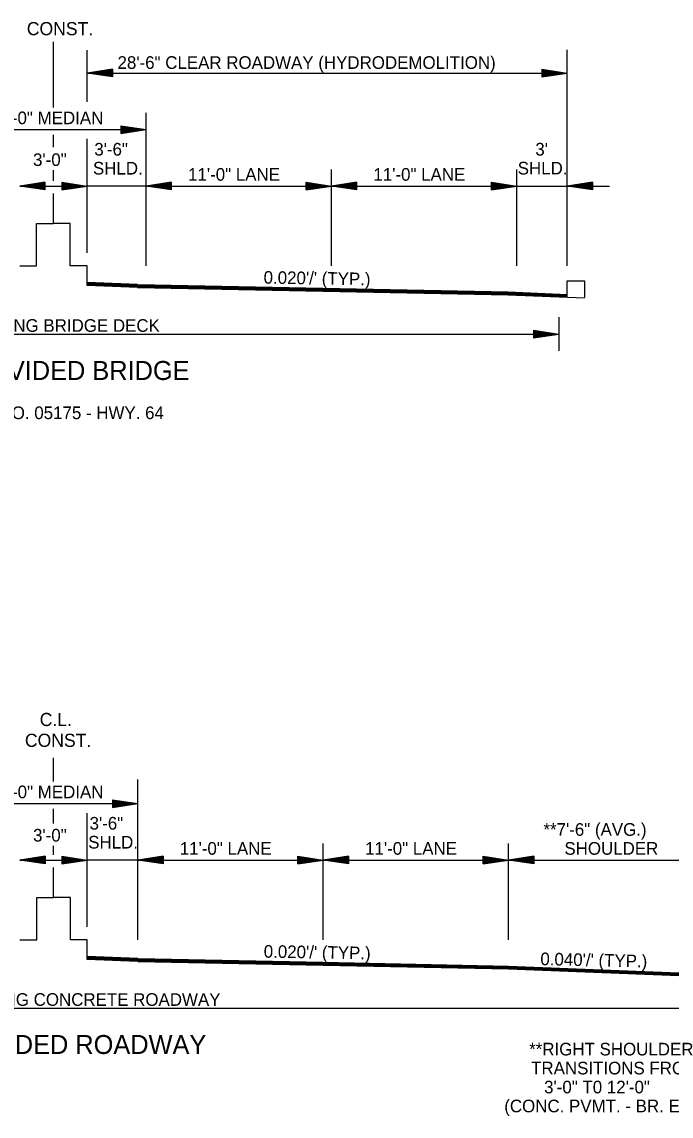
# Model space of a CAD drawing. Extents: x 542112 to 1930787, y -1968972 to 596640.
# Drawn here: x 544863 to 545248, y -1953261 to -1952611 of the extents above; entities that cross this region are included whole.
import ezdxf

# ---------------------------------------------------------------- set-up
doc = ezdxf.new("R2010")
doc.units = 0
doc.layers.add('R_Border', color=7, linetype='Continuous')
doc.layers.add('R_Draft', color=7, linetype='Continuous')

msp = doc.modelspace()

# ---------------------------------------------------------------- linework, layer by layer
at = {"layer": 'R_Border'}
for p, q in [((545186.68, -1952774.54), (545186.68, -1952765.13)), ((545186.68, -1952765.13), (545196.85, -1952765.13)), ((545196.85, -1952765.13), (545196.85, -1952774.95))]:
    msp.add_line(p, q, dxfattribs=at)
at = {"layer": 'R_Draft'}
for p, q in [((544881.74, -1952631.13), (544881.74, -1952623.28)), ((544901.68, -1952658.9), (544901.68, -1952628.12)), ((545186.68, -1952756.22), (545186.68, -1952627.93)), ((544881.74, -1952662.18), (544881.74, -1952631.13)), ((544916.68, -1952639.48), (544901.68, -1952641.73)), ((544916.68, -1952639.86), (544904.19, -1952641.73)), ((544916.68, -1952640.24), (544906.77, -1952641.73)), ((544916.68, -1952640.62), (544909.27, -1952641.73)), ((544916.68, -1952641.01), (544911.81, -1952641.73)), ((544916.68, -1952639.48), (544916.68, -1952643.98)), ((545171.68, -1952639.48), (545186.68, -1952641.73)), ((545171.68, -1952639.48), (545171.68, -1952643.98)), ((545171.68, -1952639.86), (545184.18, -1952641.73)), ((545171.68, -1952640.24), (545181.6, -1952641.73)), ((545171.68, -1952640.62), (545179.1, -1952641.73)), ((545171.68, -1952641.01), (545176.56, -1952641.73)), ((544901.68, -1952641.73), (545181.68, -1952641.73)), ((544916.68, -1952643.98), (544901.68, -1952641.73)), ((544916.68, -1952643.61), (544904.19, -1952641.73)), ((544916.68, -1952643.23), (544906.77, -1952641.73)), ((544916.68, -1952642.85), (544909.27, -1952641.73)), ((544916.68, -1952642.47), (544911.81, -1952641.73)), ((544916.68, -1952641.38), (544914.31, -1952641.73)), ((544916.68, -1952642.09), (544914.31, -1952641.73)), ((545171.68, -1952641.38), (545174.05, -1952641.73)), ((545171.68, -1952643.98), (545186.68, -1952641.73)), ((545171.68, -1952642.47), (545176.56, -1952641.73)), ((545171.68, -1952643.23), (545181.6, -1952641.73)), ((545171.68, -1952643.61), (545184.18, -1952641.73)), ((545171.68, -1952642.85), (545179.1, -1952641.73)), ((545171.68, -1952642.09), (545174.05, -1952641.73)), ((544936.68, -1952756.22), (544936.68, -1952665.38)), ((544921.68, -1952673.02), (544936.68, -1952675.27)), ((544921.68, -1952673.02), (544921.68, -1952677.52)), ((544921.68, -1952673.4), (544934.18, -1952675.27)), ((544831.68, -1952675.27), (544931.68, -1952675.27)), ((544881.68, -1952685.69), (544881.68, -1952678.38)), ((544921.68, -1952673.78), (544931.6, -1952675.27)), ((544921.68, -1952674.15), (544929.1, -1952675.27)), ((544921.68, -1952674.54), (544926.56, -1952675.27)), ((544921.68, -1952674.92), (544924.05, -1952675.27)), ((544921.68, -1952677.52), (544936.68, -1952675.27)), ((544921.68, -1952676.01), (544926.56, -1952675.27)), ((544921.68, -1952676.76), (544931.6, -1952675.27)), ((544921.68, -1952677.15), (544934.18, -1952675.27)), ((544921.68, -1952676.39), (544929.1, -1952675.27)), ((544921.68, -1952675.62), (544924.05, -1952675.27)), ((544901.68, -1952748.49), (544901.68, -1952680.74)), ((544881.68, -1952705.73), (544881.68, -1952699.28)), ((545046.68, -1952756.22), (545046.68, -1952698.92)), ((545156.68, -1952756.22), (545156.68, -1952698.92)), ((544876.68, -1952706.56), (544861.68, -1952708.81)), ((544876.68, -1952711.06), (544861.68, -1952708.81)), ((544861.68, -1952708.81), (544901.68, -1952708.81)), ((544876.68, -1952706.93), (544864.19, -1952708.81)), ((544876.68, -1952710.68), (544864.19, -1952708.81)), ((544876.68, -1952707.32), (544866.77, -1952708.81)), ((544876.68, -1952710.3), (544866.77, -1952708.81)), ((544876.68, -1952707.69), (544869.27, -1952708.81)), ((544876.68, -1952709.93), (544869.27, -1952708.81)), ((544876.68, -1952708.08), (544871.81, -1952708.81)), ((544876.68, -1952709.54), (544871.81, -1952708.81)), ((544876.68, -1952708.46), (544874.31, -1952708.81)), ((544876.68, -1952709.16), (544874.31, -1952708.81)), ((544876.68, -1952706.56), (544876.68, -1952711.06)), ((544886.68, -1952706.56), (544901.68, -1952708.81)), ((544886.68, -1952706.56), (544886.68, -1952711.06)), ((544886.68, -1952706.93), (544899.18, -1952708.81)), ((544886.68, -1952707.32), (544896.6, -1952708.81)), ((544886.68, -1952707.69), (544894.1, -1952708.81)), ((544886.68, -1952708.08), (544891.56, -1952708.81)), ((544886.68, -1952708.46), (544889.05, -1952708.81)), ((544886.68, -1952711.06), (544901.68, -1952708.81)), ((544886.68, -1952709.54), (544891.56, -1952708.81)), ((544886.68, -1952710.3), (544896.6, -1952708.81)), ((544886.68, -1952710.68), (544899.18, -1952708.81)), ((544886.68, -1952709.93), (544894.1, -1952708.81)), ((544886.68, -1952709.16), (544889.05, -1952708.81)), ((544936.68, -1952708.81), (544901.68, -1952708.81)), ((544951.68, -1952706.56), (544936.68, -1952708.81)), ((544951.68, -1952711.06), (544936.68, -1952708.81)), ((544936.68, -1952708.81), (545046.68, -1952708.81)), ((544951.68, -1952706.93), (544939.19, -1952708.81)), ((544951.68, -1952710.68), (544939.19, -1952708.81)), ((544951.68, -1952707.32), (544941.77, -1952708.81)), ((544951.68, -1952710.3), (544941.77, -1952708.81)), ((544951.68, -1952707.69), (544944.27, -1952708.81)), ((544951.68, -1952709.93), (544944.27, -1952708.81)), ((544951.68, -1952708.08), (544946.81, -1952708.81)), ((544951.68, -1952709.54), (544946.81, -1952708.81)), ((544951.68, -1952708.46), (544949.31, -1952708.81)), ((544951.68, -1952709.16), (544949.31, -1952708.81)), ((544951.68, -1952706.56), (544951.68, -1952711.06)), ((545031.68, -1952706.56), (545046.68, -1952708.81)), ((545031.68, -1952711.06), (545031.68, -1952706.56)), ((545031.68, -1952706.93), (545044.18, -1952708.81)), ((545031.68, -1952707.32), (545041.6, -1952708.81)), ((545031.68, -1952707.69), (545039.1, -1952708.81)), ((545031.68, -1952708.07), (545036.56, -1952708.81)), ((545031.68, -1952708.46), (545034.05, -1952708.81)), ((545031.68, -1952711.06), (545046.68, -1952708.81)), ((545031.68, -1952709.54), (545036.56, -1952708.81)), ((545031.68, -1952710.3), (545041.6, -1952708.81)), ((545031.68, -1952710.68), (545044.18, -1952708.81)), ((545031.68, -1952709.93), (545039.1, -1952708.81)), ((545031.68, -1952709.16), (545034.05, -1952708.81)), ((545061.68, -1952706.56), (545046.68, -1952708.81)), ((545061.68, -1952711.06), (545046.68, -1952708.81)), ((545046.68, -1952708.81), (545156.68, -1952708.81)), ((545061.68, -1952706.93), (545049.19, -1952708.81)), ((545061.68, -1952710.68), (545049.19, -1952708.81)), ((545061.68, -1952707.32), (545051.77, -1952708.81)), ((545061.68, -1952710.3), (545051.77, -1952708.81)), ((545061.68, -1952707.69), (545054.27, -1952708.81)), ((545061.68, -1952709.93), (545054.27, -1952708.81)), ((545061.68, -1952708.08), (545056.81, -1952708.81)), ((545061.68, -1952709.54), (545056.81, -1952708.81)), ((545061.68, -1952708.46), (545059.31, -1952708.81)), ((545061.68, -1952709.16), (545059.31, -1952708.81)), ((545061.68, -1952706.56), (545061.68, -1952711.06)), ((545141.68, -1952706.56), (545156.68, -1952708.81)), ((545141.68, -1952711.06), (545141.68, -1952706.56)), ((545141.68, -1952706.93), (545154.18, -1952708.81)), ((545141.68, -1952707.32), (545151.6, -1952708.81)), ((545141.68, -1952707.69), (545149.1, -1952708.81)), ((545141.68, -1952708.07), (545146.56, -1952708.81)), ((545141.68, -1952708.46), (545144.05, -1952708.81)), ((545141.68, -1952711.06), (545156.68, -1952708.81)), ((545141.68, -1952709.54), (545146.56, -1952708.81)), ((545141.68, -1952710.3), (545151.6, -1952708.81)), ((545141.68, -1952710.68), (545154.18, -1952708.81)), ((545141.68, -1952709.93), (545149.1, -1952708.81)), ((545141.68, -1952709.16), (545144.05, -1952708.81)), ((545156.68, -1952708.81), (545186.68, -1952708.81)), ((545201.68, -1952706.56), (545186.68, -1952708.81)), ((545201.68, -1952711.06), (545186.68, -1952708.81)), ((545186.68, -1952708.81), (545211.68, -1952708.81)), ((545201.68, -1952706.93), (545189.19, -1952708.81)), ((545201.68, -1952710.68), (545189.19, -1952708.81)), ((545201.68, -1952707.32), (545191.77, -1952708.81)), ((545201.68, -1952710.3), (545191.77, -1952708.81)), ((545201.68, -1952707.69), (545194.27, -1952708.81)), ((545201.68, -1952709.93), (545194.27, -1952708.81)), ((545201.68, -1952708.08), (545196.81, -1952708.81)), ((545201.68, -1952709.54), (545196.81, -1952708.81)), ((545201.68, -1952708.46), (545199.31, -1952708.81)), ((545201.68, -1952709.16), (545199.31, -1952708.81)), ((545201.68, -1952706.56), (545201.68, -1952711.06)), ((544881.68, -1952731.06), (544881.68, -1952713.19)), ((544901.68, -1952767.74), (544901.68, -1952756.07)), ((544931.7, -1952767.27), (544901.68, -1952766.07)), ((544931.68, -1952767.57), (544901.68, -1952766.37)), ((544931.68, -1952767.87), (544901.68, -1952766.67)), ((544931.67, -1952768.17), (544901.68, -1952766.97)), ((544931.66, -1952768.47), (544901.68, -1952767.27)), ((544931.65, -1952768.77), (544901.68, -1952767.57)), ((544931.65, -1952768.94), (544901.68, -1952767.74)), ((544931.65, -1952768.77), (545041.67, -1952770.97)), ((544931.65, -1952768.94), (545041.66, -1952771.14)), ((544931.66, -1952768.47), (545041.67, -1952770.67)), ((544931.67, -1952768.17), (545041.68, -1952770.37)), ((544931.68, -1952767.87), (545041.68, -1952770.07)), ((544931.7, -1952767.27), (545041.7, -1952769.47)), ((544931.7, -1952767.57), (545041.69, -1952769.77)), ((545041.67, -1952770.67), (545151.67, -1952772.87)), ((545041.67, -1952770.97), (545151.67, -1952773.17)), ((545041.68, -1952770.07), (545151.68, -1952772.27)), ((545041.68, -1952770.37), (545151.68, -1952772.57)), ((545041.69, -1952769.77), (545151.69, -1952771.97)), ((545041.7, -1952769.47), (545151.7, -1952771.67)), ((545041.66, -1952771.14), (545151.66, -1952773.34)), ((545151.7, -1952771.67), (545186.68, -1952773.07)), ((545151.7, -1952771.97), (545186.68, -1952773.37)), ((545151.7, -1952772.27), (545186.68, -1952773.67)), ((545151.7, -1952772.57), (545186.68, -1952773.97)), ((545151.7, -1952772.87), (545186.68, -1952774.27)), ((545151.7, -1952773.17), (545186.68, -1952774.57)), ((545151.7, -1952773.34), (545196.85, -1952775.15)), ((545181.66, -1952786.63), (545181.66, -1952806.63)), ((544581.66, -1952796.63), (545181.66, -1952796.63)), ((545166.66, -1952794.38), (545181.66, -1952796.63)), ((545166.66, -1952794.38), (545166.66, -1952798.88)), ((545166.66, -1952794.76), (545179.16, -1952796.63)), ((545166.66, -1952795.14), (545176.58, -1952796.63)), ((545166.66, -1952795.51), (545174.08, -1952796.63)), ((545166.66, -1952795.9), (545171.54, -1952796.63)), ((545166.66, -1952796.28), (545169.03, -1952796.63)), ((545166.66, -1952798.88), (545181.66, -1952796.63)), ((545166.66, -1952797.37), (545171.54, -1952796.63)), ((545166.66, -1952798.12), (545176.58, -1952796.63)), ((545166.66, -1952798.51), (545179.16, -1952796.63)), ((545166.66, -1952797.75), (545174.08, -1952796.63)), ((545166.66, -1952796.98), (545169.03, -1952796.63)), ((544881.83, -1953062.18), (544881.82, -1953048.2)), ((544931.77, -1953156.22), (544931.77, -1953061.01)), ((544831.77, -1953075.27), (544931.77, -1953075.27)), ((544916.77, -1953073.02), (544931.77, -1953075.27)), ((544916.77, -1953073.02), (544916.77, -1953077.52)), ((544916.77, -1953073.4), (544929.26, -1953075.27)), ((544916.77, -1953073.78), (544926.68, -1953075.27)), ((544916.77, -1953074.15), (544924.18, -1953075.27)), ((544916.77, -1953074.54), (544921.64, -1953075.27)), ((544916.77, -1953074.92), (544919.14, -1953075.27)), ((544916.77, -1953077.52), (544931.77, -1953075.27)), ((544916.77, -1953076.01), (544921.64, -1953075.27)), ((544916.77, -1953076.76), (544926.68, -1953075.27)), ((544916.77, -1953077.15), (544929.26, -1953075.27)), ((544916.77, -1953076.39), (544924.18, -1953075.27)), ((544916.77, -1953075.62), (544919.14, -1953075.27)), ((544881.77, -1953087.01), (544881.77, -1953078.38)), ((544901.77, -1953148.49), (544901.77, -1953080.96)), ((544881.77, -1953105.73), (544881.77, -1953100.42)), ((545041.77, -1953156.22), (545041.77, -1953098.92)), ((545151.77, -1953156.22), (545151.77, -1953098.92)), ((544876.77, -1953106.56), (544861.77, -1953108.81)), ((544876.77, -1953106.93), (544864.27, -1953108.81)), ((544876.77, -1953107.32), (544866.85, -1953108.81)), ((544876.77, -1953107.69), (544869.35, -1953108.81)), ((544876.77, -1953108.08), (544871.89, -1953108.81)), ((544876.77, -1953108.46), (544874.4, -1953108.81)), ((544876.77, -1953106.56), (544876.77, -1953111.06)), ((544886.77, -1953106.56), (544901.77, -1953108.81)), ((544886.77, -1953106.56), (544886.77, -1953111.06)), ((544886.77, -1953106.93), (544899.26, -1953108.81)), ((544886.77, -1953107.32), (544896.68, -1953108.81)), ((544886.77, -1953107.69), (544894.18, -1953108.81)), ((544886.77, -1953108.08), (544891.64, -1953108.81)), ((544886.77, -1953108.46), (544889.14, -1953108.81)), ((544946.77, -1953106.56), (544931.77, -1953108.81)), ((544946.77, -1953106.93), (544934.27, -1953108.81)), ((544946.77, -1953107.32), (544936.85, -1953108.81)), ((544946.77, -1953107.69), (544939.35, -1953108.81)), ((544946.77, -1953108.08), (544941.89, -1953108.81)), ((544946.77, -1953108.46), (544944.4, -1953108.81)), ((544946.77, -1953106.56), (544946.77, -1953111.06)), ((545026.77, -1953106.56), (545041.77, -1953108.81)), ((545026.77, -1953111.06), (545026.77, -1953106.56)), ((545026.77, -1953106.93), (545039.26, -1953108.81)), ((545026.77, -1953107.32), (545036.68, -1953108.81)), ((545026.77, -1953107.69), (545034.18, -1953108.81)), ((545026.77, -1953108.07), (545031.64, -1953108.81)), ((545026.77, -1953108.46), (545029.14, -1953108.81)), ((545056.77, -1953106.56), (545041.77, -1953108.81)), ((545056.77, -1953106.93), (545044.27, -1953108.81)), ((545056.77, -1953107.32), (545046.85, -1953108.81)), ((545056.77, -1953107.69), (545049.35, -1953108.81)), ((545056.77, -1953108.08), (545051.89, -1953108.81)), ((545056.77, -1953108.46), (545054.4, -1953108.81)), ((545056.77, -1953106.56), (545056.77, -1953111.06)), ((545136.77, -1953106.56), (545151.77, -1953108.81)), ((545136.77, -1953111.06), (545136.77, -1953106.56)), ((545136.77, -1953106.93), (545149.26, -1953108.81)), ((545136.77, -1953107.32), (545146.68, -1953108.81)), ((545136.77, -1953107.69), (545144.18, -1953108.81)), ((545136.77, -1953108.07), (545141.64, -1953108.81)), ((545136.77, -1953108.46), (545139.14, -1953108.81)), ((545166.77, -1953106.56), (545151.77, -1953108.81)), ((545166.77, -1953106.93), (545154.27, -1953108.81)), ((545166.77, -1953107.32), (545156.85, -1953108.81)), ((545166.77, -1953107.69), (545159.35, -1953108.81)), ((545166.77, -1953108.08), (545161.89, -1953108.81)), ((545166.77, -1953108.46), (545164.4, -1953108.81)), ((545166.77, -1953106.56), (545166.77, -1953111.06)), ((544876.77, -1953111.06), (544861.77, -1953108.81)), ((544861.77, -1953108.81), (544901.77, -1953108.81)), ((544876.77, -1953110.68), (544864.27, -1953108.81)), ((544876.77, -1953110.3), (544866.85, -1953108.81)), ((544876.77, -1953109.93), (544869.35, -1953108.81)), ((544876.77, -1953109.54), (544871.89, -1953108.81)), ((544876.77, -1953109.16), (544874.4, -1953108.81)), ((544881.77, -1953131.06), (544881.77, -1953113.19)), ((544886.77, -1953111.06), (544901.77, -1953108.81)), ((544886.77, -1953109.54), (544891.64, -1953108.81)), ((544886.77, -1953110.3), (544896.68, -1953108.81)), ((544886.77, -1953110.68), (544899.26, -1953108.81)), ((544886.77, -1953109.93), (544894.18, -1953108.81)), ((544886.77, -1953109.16), (544889.14, -1953108.81)), ((544931.77, -1953108.81), (544901.77, -1953108.81)), ((544946.77, -1953111.06), (544931.77, -1953108.81)), ((544931.77, -1953108.81), (545041.77, -1953108.81)), ((544946.77, -1953110.68), (544934.27, -1953108.81)), ((544946.77, -1953110.3), (544936.85, -1953108.81)), ((544946.77, -1953109.93), (544939.35, -1953108.81)), ((544946.77, -1953109.54), (544941.89, -1953108.81)), ((544946.77, -1953109.16), (544944.4, -1953108.81)), ((545026.77, -1953111.06), (545041.77, -1953108.81)), ((545026.77, -1953109.54), (545031.64, -1953108.81)), ((545026.77, -1953110.3), (545036.68, -1953108.81)), ((545026.77, -1953110.68), (545039.26, -1953108.81)), ((545026.77, -1953109.93), (545034.18, -1953108.81)), ((545026.77, -1953109.16), (545029.14, -1953108.81)), ((545056.77, -1953111.06), (545041.77, -1953108.81)), ((545041.77, -1953108.81), (545151.77, -1953108.81)), ((545056.77, -1953110.68), (545044.27, -1953108.81)), ((545056.77, -1953110.3), (545046.85, -1953108.81)), ((545056.77, -1953109.93), (545049.35, -1953108.81)), ((545056.77, -1953109.54), (545051.89, -1953108.81)), ((545056.77, -1953109.16), (545054.4, -1953108.81)), ((545136.77, -1953111.06), (545151.77, -1953108.81)), ((545136.77, -1953109.54), (545141.64, -1953108.81)), ((545136.77, -1953110.3), (545146.68, -1953108.81)), ((545136.77, -1953110.68), (545149.26, -1953108.81)), ((545136.77, -1953109.93), (545144.18, -1953108.81)), ((545136.77, -1953109.16), (545139.14, -1953108.81)), ((545151.77, -1953108.81), (545271.77, -1953108.81)), ((545166.77, -1953111.06), (545151.77, -1953108.81)), ((545166.77, -1953110.68), (545154.27, -1953108.81)), ((545166.77, -1953110.3), (545156.85, -1953108.81)), ((545166.77, -1953109.93), (545159.35, -1953108.81)), ((545166.77, -1953109.54), (545161.89, -1953108.81)), ((545166.77, -1953109.16), (545164.4, -1953108.81)), ((544901.77, -1953167.74), (544901.77, -1953156.07)), ((544931.78, -1953167.27), (544901.77, -1953166.07)), ((544931.77, -1953167.57), (544901.77, -1953166.37)), ((544931.76, -1953167.87), (544901.77, -1953166.67)), ((544931.75, -1953168.17), (544901.77, -1953166.97)), ((544931.74, -1953168.47), (544901.77, -1953167.27)), ((544931.73, -1953168.77), (544901.77, -1953167.57)), ((544931.73, -1953168.94), (544901.77, -1953167.74)), ((544931.73, -1953168.77), (545041.75, -1953170.97)), ((544931.73, -1953168.94), (545041.75, -1953171.14)), ((544931.74, -1953168.47), (545041.75, -1953170.67)), ((544931.75, -1953168.17), (545041.76, -1953170.37)), ((544931.76, -1953167.87), (545041.77, -1953170.07)), ((544931.78, -1953167.27), (545041.78, -1953169.47)), ((544931.78, -1953167.57), (545041.77, -1953169.77)), ((545041.75, -1953170.67), (545151.75, -1953172.87)), ((545041.75, -1953170.97), (545151.75, -1953173.17)), ((545041.75, -1953171.14), (545151.75, -1953173.34)), ((545041.76, -1953170.37), (545151.76, -1953172.57)), ((545041.77, -1953169.77), (545151.77, -1953171.97)), ((545041.77, -1953170.07), (545151.77, -1953172.27)), ((545041.78, -1953169.47), (545151.78, -1953171.67)), ((545151.77, -1953171.67), (545271.77, -1953176.47)), ((545151.77, -1953171.97), (545271.77, -1953176.77)), ((545151.77, -1953172.27), (545271.77, -1953177.07)), ((545151.77, -1953172.57), (545271.77, -1953177.37)), ((545151.77, -1953172.87), (545271.77, -1953177.67)), ((545151.77, -1953173.17), (545271.77, -1953177.97)), ((545151.77, -1953173.34), (545271.77, -1953178.14)), ((544491.77, -1953196.63), (545271.77, -1953196.63))]:
    msp.add_line(p, q, dxfattribs=at)
for points in [[(544861.68, -1952756.06), (544871.68, -1952756.06), (544871.68, -1952731.06), (544881.68, -1952731.06)], [(544901.68, -1952756.06), (544891.68, -1952756.06), (544891.68, -1952731.06), (544881.68, -1952731.06)], [(544861.77, -1953156.06), (544871.77, -1953156.06), (544871.77, -1953131.06), (544881.77, -1953131.06)], [(544901.77, -1953156.06), (544891.77, -1953156.06), (544891.77, -1953131.06), (544881.77, -1953131.06)]]:
    msp.add_lwpolyline(points, dxfattribs=at)

# ---------------------------------------------------------------- texts
for s, height, p in [('CONST.', 7.8, (544865.9, -1952619.29)), ('28\'-6" CLEAR ROADWAY (HYDRODEMOLITION)', 7.5, (544919.74, -1952639.26)), ('10\'-0" MEDIAN', 7.5, (544843.98, -1952672.1)), ('3\'-6" ', 7.5, (544905.96, -1952690.71)), ("3' ", 7.5, (545167.73, -1952690.69)), ('3\'-0"', 7.5, (544869.61, -1952696.9)), ('SHLD.', 7.5, (544905.17, -1952701.96)), ('11\'-0" LANE', 7.5, (544961.63, -1952705.64)), ('11\'-0" LANE', 7.5, (545071.63, -1952705.64)), ('SHLD.', 7.5, (545157.28, -1952701.94)), ('60\'-0" EXISTING BRIDGE DECK', 7.5, (544797.83, -1952795.31)), ('4 LANE DIVIDED BRIDGE', 11.25, (544783.59, -1952823.87)), ('9 - BR. NO. 05175 - HWY. 64', 7.5, (544815.74, -1952847.12)), ('C.L.', 7.8, (544873.56, -1953029.26)), ('CONST.', 7.8, (544864.77, -1953041.63)), ('10\'-0" MEDIAN', 7.5, (544844.06, -1953072.1)), ('3\'-6" ', 7.5, (544903.15, -1953090.71)), ('**7\'-6" (AVG.) ', 7.5, (545172.55, -1953094.39)), ('3\'-0"', 7.5, (544869.61, -1953097.81)), ('SHLD.', 7.5, (544902.36, -1953101.96)), ('11\'-0" LANE', 7.5, (544956.71, -1953105.64)), ('11\'-0" LANE', 7.5, (545066.71, -1953105.64)), ('SHOULDER', 7.5, (545184.99, -1953105.64)), ('69\'-0" (AVG.) EXISTING CONCRETE ROADWAY', 7.5, (544758.61, -1953195.31)), ('4 LANE DIVIDED ROADWAY', 11.25, (544773.49, -1953223.87)), (' **RIGHT SHOULDER', 7.5, (545161.29, -1953224.75)), ('TRANSITIONS FROM ', 7.5, (545165.24, -1953236)), ('3\'-0" T0 12\'-0"', 7.5, (545172.95, -1953247.25)), ('(CONC. PVMT. - BR. EXIT)', 7.5, (545149.3, -1953258.5))]:
    msp.add_text(s, height=height, dxfattribs=at).set_placement(p)
for s, rotation, p in [("0.020'/' (TYP.)", 359.02808, (545006.4, -1952766.7)), ("0.020'/' (TYP.)", 359.02808, (545006.48, -1953166.7)), ("0.040'/' (TYP.)", 358.68162, (545170.65, -1953171.15))]:
    msp.add_text(s, height=7.5, rotation=rotation, dxfattribs=at).set_placement(p)

doc.saveas('drawing.dxf')
